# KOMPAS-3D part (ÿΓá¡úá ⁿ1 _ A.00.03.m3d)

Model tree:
1. Эскиз:1
2. Операция выдавливания:1
     Расстояние 1 = 150; Расстояние 2 = 5
3. Эскиз:2
4. Вырезать элемент выдавливания:1
     Расстояние 1 = 50
5. Эскиз:3
6. Вырезать элемент выдавливания:2
     Расстояние 1 = 20
7. Эскиз:5
8. Вырезать элемент выдавливания:4
     Расстояние 1 = 58.4
9. Эскиз:6
10. Операция выдавливания:2
     Расстояние 1 = 160; Расстояние 2 = 50
11. Эскиз:7
12. Вырезать элемент выдавливания:5
     Расстояние 1 = 30

Referenced files in C:\Program Files (x86)\ASCON\KOMPAS-3D V15\Libs\PartLib\DATA\vault\Methods\Kompas\3D\: PLib_Nut_OST92_900.m3d
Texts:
  Штанга №1
  Гайка М10-6H ГОСТ 2524-70
  bcut1
  hole1
  hcut1
  hole2
  cut1
  (-) Гайка М10-6H ГОСТ 2524-70
  ГОСТ 2524-70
